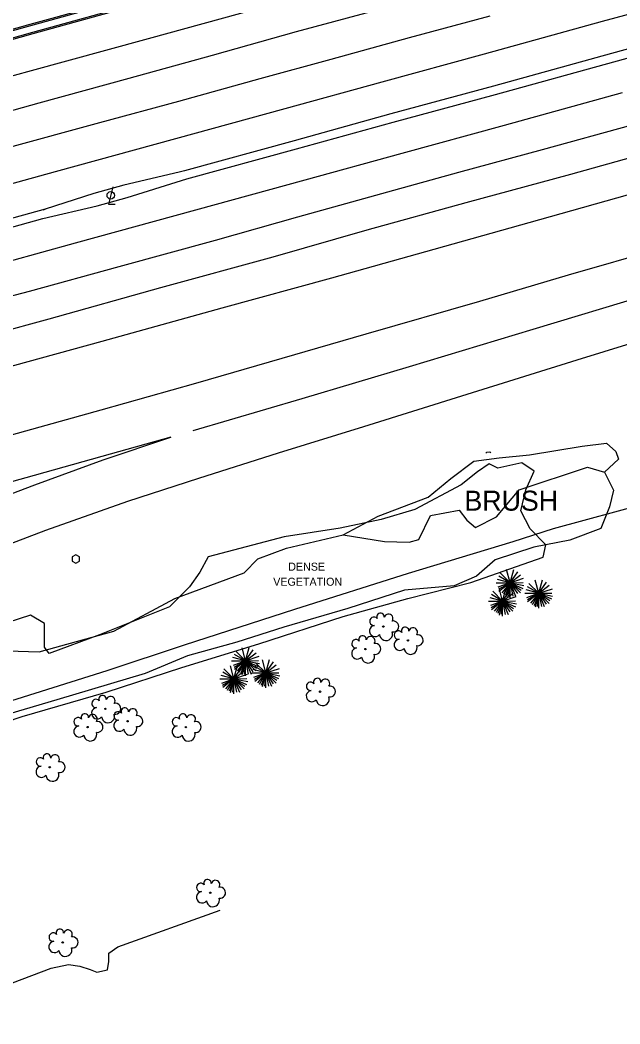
# Model space of a CAD drawing. Extents: x 2129547 to 2134906, y 657330 to 659734.
# Drawn here: x 2133105.8 to 2133315.8, y 658417.8 to 658769 of the extents above; entities that cross this region are included whole.
import ezdxf

# ---------------------------------------------------------------- set-up
doc = ezdxf.new("R2010")
doc.units = 0
for name, color, linetype in [('Default', 7, 'Continuous'), ('DR_X_Culvert', 7, 'Continuous'), ('LT_X_Poles', 7, 'Continuous'), ('PM_X_Edge_Line', 7, 'Continuous'), ('PM_X_Lane_Line', 7, 'Continuous'), ('PV_X_Curb', 7, 'Continuous'), ('PV_X_EOP2', 7, 'Continuous'), ('PV_X_Parking_Lot', 7, 'Continuous'), ('PV_X_Shoulder', 7, 'Continuous'), ('RD_X_Cells', 7, 'Continuous'), ('RD_X_Concrete_Barrier', 7, 'Continuous'), ('RD_X_Fence', 7, 'Continuous'), ('RD_X_Misc_Items', 7, 'Continuous'), ('VG_X_Cells', 7, 'Continuous'), ('VG_X_Shrub_Line_Lt', 7, 'Continuous'), ('VG_X_Text', 7, 'Continuous'), ('VG_X_Tree_Line_Lt', 7, 'Continuous')]:
    doc.layers.add(name, color=color, linetype=linetype)

# ---------------------------------------------------------------- blocks, each defined once
blk = doc.blocks.new('CULVERT')
at = {"layer": 'Default'}
blk.add_lwpolyline([(-0.0508, 0.1143), (0, 0.0635), (0, -0.0635), (-0.0508, -0.1143)], dxfattribs=at)
blk = doc.blocks.new('LPOLE')
at = {"layer": 'LT_X_Poles'}
blk.add_lwpolyline([(0.01, 0.0375), (-0.01, -0.0385), (0.02, -0.0385)], dxfattribs=at)
blk.add_circle((0, 0), 0.0165, dxfattribs=at)
blk = doc.blocks.new('POST')
at = {"layer": 'RD_X_Cells'}
blk.add_lwpolyline([(-0.0165, -0.0095), (0, -0.019), (0.0165, -0.0095), (0.0165, 0.0095), (0, 0.019), (-0.0165, 0.0095), (-0.0165, -0.0095)], dxfattribs=at)
blk = doc.blocks.new('TREE')
at = {"layer": 'VG_X_Cells'}
blk.add_circle((0, 0), 0.00305, dxfattribs=at)
for centre, radius, start, end in [((-0.0125, 0.0428), 0.0167, 354.0047, 205.9741), ((0.0232, 0.0359), 0.0197, 323.83, 165.0376), ((-0.0362, -0.0197), 0.0251, 96.1722, 320.5737), ((-0.042, 0.0237), 0.0187, 39.0625, 279.5412), ((0.0439, 0.0005), 0.0243, 259.1453, 101.4596), ((0.012, -0.0331), 0.029, 184.9476, 19.4572)]:
    blk.add_arc(centre, radius, start, end, dxfattribs=at)
blk = doc.blocks.new('ETREE')
at = {"layer": 'VG_X_Cells'}
for p, q in [((0, 0), (-0.0157, 0.0586)), ((0, 0), (0.016, 0.0597)), ((0, 0), (0.0337, 0.0493)), ((-0.0627, 0), (0, 0)), ((0, 0), (-0.056, 0.015)), ((0, 0), (-0.0545, -0.0198)), ((0, 0), (-0.0506, -0.029)), ((0, 0), (-0.0496, 0.0292)), ((0, 0), (-0.0496, -0.038)), ((0, 0), (-0.0443, 0.0443)), ((0, 0), (-0.0374, -0.044)), ((0, 0), (-0.0294, -0.051)), ((0, 0), (-0.0211, -0.0551)), ((0, 0), (-0.016, -0.0617)), ((0, 0), (-0.0069, -0.0583)), ((0, 0), (0.0464, 0.0356)), ((0, 0), (0.0602, 0.0204)), ((0, 0), (0.0573, 0.0012)), ((0, -0.0665), (0, 0)), ((0, 0), (0.0117, -0.0589)), ((0, 0), (0.0246, -0.0593)), ((0, 0), (0.0322, -0.0482)), ((0, 0), (0.0456, -0.0447)), ((0, 0), (0.0485, -0.0324)), ((0, 0), (0.0567, -0.0247)), ((0, 0), (0.0613, -0.0122))]:
    blk.add_line(p, q, dxfattribs=at)

msp = doc.modelspace()

# ---------------------------------------------------------------- linework, layer by layer
at = {"layer": 'PM_X_Edge_Line'}
for points in [[(2132528.76, 658591.3), (2132572.65, 658603.2), (2132602.55, 658611.29), (2132644.66, 658622.9), (2132678.49, 658632.23), (2132709.33, 658640.79), (2132742.09, 658649.84), (2132779.08, 658660.22), (2132814.09, 658669.97), (2132851.16, 658680.16), (2132885.72, 658689.68), (2132917.4, 658698.33), (2132953.49, 658708.38), (2132988.45, 658717.87), (2133023.88, 658727.48), (2133061.03, 658737.93), (2133108.53, 658751.04), (2133150.67, 658762.63), (2133188.97, 658773.11), (2133222.93, 658782.47), (2133258.8, 658792.21), (2133300.07, 658803.6), (2133337.89, 658813.96)], [(2132751.82, 658614.87), (2132788.85, 658625.26), (2132823.77, 658634.98), (2132860.8, 658645.16), (2132895.33, 658654.67), (2132927.05, 658663.34), (2132963.11, 658673.38), (2132997.96, 658682.83), (2133033.55, 658692.49), (2133070.77, 658702.96), (2133118.17, 658716.04), (2133160.28, 658727.62), (2133198.58, 658738.11), (2133232.5, 658747.46), (2133268.38, 658757.19), (2133309.7, 658768.6), (2133347.5, 658778.96)], [(2133316.59, 658743.53), (2133275.25, 658732.12), (2133239.36, 658722.38), (2133205.47, 658713.04), (2133167.16, 658702.55), (2133125.07, 658690.98), (2133077.75, 658677.91), (2133040.47, 658667.43), (2133004.77, 658657.74), (2132970.01, 658648.31), (2132933.96, 658638.28), (2132902.2, 658629.6), (2132867.7, 658620.1), (2132830.71, 658609.93), (2132795.85, 658600.22), (2132736.97, 658584.29), (2132686.86, 658570.47), (2132647.78, 658559.73), (2132616.38, 658551.02), (2132587.48, 658543.23), (2132543.98, 658531.22), (2132527.44, 658526.61)], [(2132526.73, 658488.71), (2132530.21, 658489.67), (2132569.63, 658500.53), (2132596.17, 658508.1), (2132621.44, 658515.22), (2132661.75, 658526.36), (2132698.15, 658536.48), (2132732.1, 658545.81), (2132769.52, 658556.2), (2132805.25, 658565.98), (2132840.18, 658575.71), (2132877.13, 658585.87), (2132911.6, 658595.36), (2132943.4, 658604.05), (2132979.41, 658614.08), (2133014.06, 658623.48), (2133049.93, 658633.21), (2133087.28, 658643.72), (2133134.5, 658656.75), (2133176.55, 658668.31), (2133214.88, 658678.81), (2133247.85, 658688.07), (2133283.96, 658698.16), (2133325.94, 658709.93)], [(2133330.15, 658689.11), (2133297.63, 658679.74), (2133266.56, 658670.62), (2133226.79, 658659.12), (2133197.42, 658650.62), (2133167.14, 658641.9), (2133134.04, 658632.57), (2133102.68, 658623.78), (2133072.24, 658615.25), (2133037.61, 658605.58), (2133003.5, 658596.32), (2132971.17, 658587.53), (2132944.96, 658580.31), (2132910.44, 658570.81), (2132883.46, 658563.38), (2132856.23, 658556.06), (2132824.38, 658546.99), (2132792.59, 658538.19), (2132761.91, 658529.84)], [(2132780.42, 658417.85), (2132794.53, 658428.85), (2132808.02, 658438.8), (2132828.29, 658452.89), (2132851.51, 658467.84), (2132872.43, 658480.36), (2132894.67, 658493.03), (2132919.61, 658506.34), (2132942.8, 658518.03), (2132970.58, 658531.41), (2132994.65, 658542.18), (2133023.55, 658554.71), (2133055.17, 658567.57), (2133087.49, 658580.23), (2133114.79, 658590.55), (2133143.49, 658600.71), (2133168.31, 658608.81), (2133196.23, 658617.63), (2133226.14, 658626.84), (2133262.28, 658638.19), (2133300.81, 658650.13), (2133340.17, 658662.31)], [(2133158.51, 658623.08), (2133137.32, 658617.18), (2133107.75, 658608.87), (2133069.12, 658598.17), (2133036.14, 658589.08), (2133001.62, 658579.74), (2132965.01, 658569.7), (2132930.32, 658560.06), (2132893.98, 658550.04), (2132857.01, 658539.9), (2132824.05, 658530.67), (2132784.28, 658519.67), (2132746.13, 658509.23), (2132706.06, 658498.15), (2132669.95, 658488.27), (2132635.09, 658478.56), (2132605.57, 658470.07), (2132586.69, 658464.73), (2132544.05, 658452.96), (2132525.87, 658448)], [(2132778.88, 658436.51), (2132797.28, 658450.31), (2132815.53, 658463.15), (2132834.09, 658475.32), (2132853.88, 658487.67), (2132874.62, 658499.37), (2132902.61, 658514.38), (2132925.64, 658526.53), (2132961.12, 658543.72), (2132996.4, 658559.86), (2133023.56, 658571.6), (2133058.45, 658586.09), (2133087.14, 658597.32), (2133091.83, 658599.15), (2133110.89, 658606.44), (2133134.83, 658615.24), (2133158.51, 658623.08)]]:
    msp.add_lwpolyline(points, dxfattribs=at)
at = {"layer": 'PM_X_Lane_Line'}
for points in [[(2132770.46, 658645.83), (2132797.06, 658653.26), (2132828.19, 658661.83), (2132861.38, 658670.87), (2132890.6, 658678.93), (2132920.35, 658687.14), (2132947.85, 658694.81), (2132974.67, 658702.08), (2133006.64, 658710.96), (2133034.51, 658718.68), (2133060.36, 658725.76), (2133088.12, 658733.33), (2133112.45, 658740.12), (2133143.94, 658748.72), (2133173.17, 658756.72), (2133202.56, 658765), (2133233.48, 658773.28)], [(2133270.18, 658770.37), (2133241.97, 658762.79), (2133214.5, 658755.19), (2133189.65, 658748.43), (2133161.27, 658740.52), (2133133.55, 658733.02), (2133100.64, 658724.1), (2133069.76, 658715.44), (2133037.24, 658706.34), (2133009.32, 658698.73), (2132981.91, 658691.14), (2132953.6, 658683.48), (2132924.09, 658675.45), (2132896.78, 658668.12), (2132864.32, 658659.21), (2132830.55, 658649.67), (2132796.16, 658640.09), (2132761.23, 658630.43)], [(2133319.94, 658732.31), (2133288.5, 658723.61), (2133259.3, 658715.66), (2133234.36, 658708.83), (2133202.83, 658700.05), (2133174.08, 658691.94), (2133140.33, 658682.75), (2133108.95, 658674.06), (2133082.6, 658667.15), (2133049.4, 658658.04), (2133018.8, 658649.85), (2132984.92, 658640.29), (2132949.38, 658630.35), (2132919.99, 658622.07), (2132890.94, 658613.99), (2132858.31, 658605.1), (2132836.54, 658599.14), (2132811.38, 658592.48), (2132777.26, 658582.97)], [(2133330.22, 658723.85), (2133298.5, 658714.96), (2133261.81, 658705.07), (2133227.15, 658695.47), (2133194.29, 658686.12), (2133154.93, 658675.36), (2133115.86, 658664.39), (2133078.14, 658654.11), (2133038.27, 658643.16), (2133002.28, 658632.99), (2132968.65, 658623.33), (2132933.53, 658613.55), (2132899.33, 658604.14), (2132864.71, 658594.55), (2132827.99, 658584.36), (2132790.39, 658574.06), (2132761.16, 658566.05), (2132724.86, 658555.97), (2132689.68, 658546.19), (2132656.96, 658537.15), (2132624.97, 658528.2), (2132593.37, 658519.4), (2132560.89, 658510.33), (2132526.97, 658501.13)], [(2133166.38, 658625.46), (2133204.56, 658636.6), (2133242.08, 658647.79), (2133285.43, 658660.84), (2133325.6, 658673.06)]]:
    msp.add_lwpolyline(points, dxfattribs=at)
at = {"layer": 'PV_X_Curb'}
for points in [[(2133354.62, 658834.11), (2133313.99, 658822.98), (2133249.15, 658805.18), (2133186.51, 658788.1), (2133148.3, 658777.86), (2133109.44, 658767.05), (2133075.85, 658757.65), (2133043.52, 658748.97), (2133012.69, 658740.69), (2132981.33, 658732.09), (2132950.79, 658723.65), (2132920.09, 658715.1), (2132889.35, 658706.83), (2132858.99, 658698.27), (2132820.58, 658687.77), (2132782.52, 658677.48), (2132742.93, 658666.63), (2132707.48, 658656.83), (2132668.28, 658645.96), (2132633.36, 658636.51), (2132602.69, 658628.08)], [(2133355.25, 658831.69), (2133314.65, 658820.57), (2133249.81, 658802.77), (2133187.16, 658785.68), (2133148.96, 658775.45), (2133110.11, 658764.65), (2133076.51, 658755.24), (2133044.17, 658746.56), (2133013.34, 658738.28), (2132981.99, 658729.68), (2132951.45, 658721.24), (2132920.75, 658712.69), (2132890.01, 658704.42), (2132859.66, 658695.87), (2132821.24, 658685.36), (2132783.18, 658675.06), (2132743.6, 658664.22), (2132708.14, 658654.42), (2132668.94, 658643.55), (2132634.02, 658634.09), (2132603.1, 658625.87)]]:
    msp.add_lwpolyline(points, dxfattribs=at)
at = {"layer": 'PV_X_EOP2'}
for points in [[(2132528.76, 658591.3), (2132572.65, 658603.2), (2132602.55, 658611.29), (2132644.66, 658622.9), (2132678.49, 658632.23), (2132709.33, 658640.79), (2132742.09, 658649.84), (2132779.08, 658660.22), (2132814.09, 658669.97), (2132851.16, 658680.16), (2132885.72, 658689.68), (2132917.4, 658698.33), (2132953.49, 658708.38), (2132988.45, 658717.87), (2133023.88, 658727.48), (2133061.03, 658737.93), (2133108.53, 658751.04), (2133150.67, 658762.63), (2133188.97, 658773.11), (2133222.93, 658782.47), (2133258.8, 658792.21), (2133300.07, 658803.6), (2133337.89, 658813.96)], [(2132751.82, 658614.87), (2132788.85, 658625.26), (2132823.77, 658634.98), (2132860.8, 658645.16), (2132895.33, 658654.67), (2132927.05, 658663.34), (2132963.11, 658673.38), (2132997.96, 658682.83), (2133033.55, 658692.49), (2133070.77, 658702.96), (2133118.17, 658716.04), (2133160.28, 658727.62), (2133198.58, 658738.11), (2133232.5, 658747.46), (2133268.38, 658757.19), (2133309.7, 658768.6), (2133347.5, 658778.96)], [(2133316.59, 658743.53), (2133275.25, 658732.12), (2133239.36, 658722.38), (2133205.47, 658713.04), (2133167.16, 658702.55), (2133125.07, 658690.98), (2133077.75, 658677.91), (2133040.47, 658667.43), (2133004.77, 658657.74), (2132970.01, 658648.31), (2132933.96, 658638.28), (2132902.2, 658629.6), (2132867.7, 658620.1), (2132830.71, 658609.93), (2132795.85, 658600.22), (2132736.97, 658584.29), (2132686.86, 658570.47), (2132647.78, 658559.73), (2132616.38, 658551.02), (2132587.48, 658543.23), (2132543.98, 658531.22), (2132527.44, 658526.61)], [(2132526.73, 658488.71), (2132530.21, 658489.67), (2132569.63, 658500.53), (2132596.17, 658508.1), (2132621.44, 658515.22), (2132661.75, 658526.36), (2132698.15, 658536.48), (2132732.1, 658545.81), (2132769.52, 658556.2), (2132805.25, 658565.98), (2132840.18, 658575.71), (2132877.13, 658585.87), (2132911.6, 658595.36), (2132943.4, 658604.05), (2132979.41, 658614.08), (2133014.06, 658623.48), (2133049.93, 658633.21), (2133087.28, 658643.72), (2133134.5, 658656.75), (2133176.55, 658668.31), (2133214.88, 658678.81), (2133247.85, 658688.07), (2133283.96, 658698.16), (2133325.94, 658709.93)], [(2133330.15, 658689.11), (2133297.63, 658679.74), (2133266.56, 658670.62), (2133226.79, 658659.12), (2133197.42, 658650.62), (2133167.14, 658641.9), (2133134.04, 658632.57), (2133102.68, 658623.78), (2133072.24, 658615.25), (2133037.61, 658605.58), (2133003.5, 658596.32), (2132971.17, 658587.53), (2132944.96, 658580.31), (2132910.44, 658570.81), (2132883.46, 658563.38), (2132856.23, 658556.06), (2132824.38, 658546.99), (2132792.59, 658538.19), (2132761.91, 658529.84)]]:
    msp.add_lwpolyline(points, dxfattribs=at)
at = {"layer": 'PV_X_Parking_Lot'}
msp.add_lwpolyline([(2133103.14, 658432.24), (2133116.7, 658437.31), (2133122.67, 658438.61), (2133126.66, 658438.11), (2133130.28, 658436.89), (2133132.68, 658435.98), (2133136.39, 658436.82), (2133136.81, 658439.63), (2133136.81, 658442.59), (2133140.02, 658444.8), (2133175.8, 658457.64)], dxfattribs=at)
at = {"layer": 'PV_X_Shoulder'}
for points in [[(2132602.56, 658628.56), (2132633.23, 658636.99), (2132668.15, 658646.45), (2132707.34, 658657.31), (2132742.8, 658667.11), (2132782.39, 658677.96), (2132820.45, 658688.26), (2132858.86, 658698.76), (2132889.22, 658707.31), (2132919.96, 658715.58), (2132950.65, 658724.13), (2132981.19, 658732.57), (2133012.56, 658741.17), (2133043.39, 658749.45), (2133075.72, 658758.13), (2133109.31, 658767.54), (2133148.17, 658778.35), (2133186.38, 658788.58), (2133249.02, 658805.67), (2133313.86, 658823.46), (2133354.5, 658834.6)], [(2133355.38, 658831.21), (2133314.78, 658820.09), (2133249.94, 658802.29), (2133187.29, 658785.2), (2133149.09, 658774.97), (2133110.25, 658764.16), (2133076.65, 658754.76), (2133044.3, 658746.07), (2133013.47, 658737.79), (2132982.12, 658729.2), (2132951.59, 658720.76), (2132920.88, 658712.21), (2132890.15, 658703.93), (2132859.8, 658695.38), (2132821.37, 658684.88), (2132783.31, 658674.58), (2132743.73, 658663.74), (2132708.28, 658653.94), (2132669.07, 658643.07), (2132634.15, 658633.61), (2132603.23, 658625.39)]]:
    msp.add_lwpolyline(points, dxfattribs=at)
at = {"layer": 'RD_X_Concrete_Barrier'}
msp.add_line((2133113.8, 658702.67), (2133114.6, 658702.92), dxfattribs=at)
for points in [[(2133350.6, 658767.68), (2133312.8, 658757.32), (2133271.47, 658745.91), (2133235.59, 658736.17), (2133201.68, 658726.83), (2133163.38, 658716.34), (2133161.51, 658715.82), (2133142.13, 658711.26), (2133131.55, 658708.34), (2133114.6, 658702.92)], [(2132733.99, 658595.19), (2132792.86, 658611.11), (2132827.69, 658620.82), (2132864.7, 658630.99), (2132899.22, 658640.5), (2132930.96, 658649.17), (2132967.01, 658659.2), (2133001.81, 658668.65), (2133037.46, 658678.32), (2133074.72, 658688.8), (2133113.76, 658699.58), (2133132.75, 658704), (2133143.27, 658706.9), (2133162.3, 658712.93), (2133164.17, 658713.44), (2133202.48, 658723.94), (2133236.38, 658733.28), (2133272.26, 658743.02), (2133313.6, 658754.43), (2133351.4, 658764.78)], [(2133114.6, 658702.92), (2133073.91, 658691.69), (2133036.67, 658681.21), (2133001.02, 658671.54), (2132966.22, 658662.09), (2132930.16, 658652.06), (2132898.42, 658643.39), (2132863.91, 658633.88), (2132826.89, 658623.71), (2132792.07, 658614.01), (2132733.2, 658598.09), (2132728.03, 658596.66), (2132708.65, 658592.09), (2132698.07, 658589.17), (2132680.32, 658583.5), (2132643.98, 658573.52), (2132612.61, 658564.81), (2132584.03, 658557.2), (2132559.64, 658550.51), (2132527.73, 658542.1)]]:
    msp.add_lwpolyline(points, dxfattribs=at)
at = {"layer": 'RD_X_Fence'}
msp.add_lwpolyline([(2133409.37, 658623.24), (2133399.25, 658620.39), (2133396.55, 658620.65), (2133384.38, 658617.74), (2133380.03, 658615.44), (2133356.03, 658608.88), (2133325.9, 658600.19), (2133292.34, 658590.99), (2133278.32, 658586.5), (2133241.59, 658575.44), (2133201.86, 658562.85), (2133163.22, 658550.3), (2133136.09, 658541.38), (2133085.63, 658525.47), (2133059.75, 658517.07), (2133037.1, 658508.29), (2133014.93, 658496.51), (2132978.92, 658478.61), (2132972.42, 658487.07)], dxfattribs=at)
at = {"layer": 'RD_X_Misc_Items'}
msp.add_lwpolyline([(2133088.23, 658519.27), (2133106.48, 658525.38), (2133135.85, 658533.94), (2133162.34, 658542.48), (2133189.4, 658550.78), (2133218.83, 658560.43), (2133241.47, 658566.72), (2133263.53, 658572.24), (2133288.9, 658581.12), (2133289.88, 658585.42), (2133284.3, 658590.99), (2133281.12, 658597.31), (2133282.78, 658604.66), (2133285.69, 658611.21), (2133281.45, 658614.18), (2133273.03, 658612.32), (2133269.98, 658613.79), (2133265.93, 658611.04), (2133260.2, 658606.49), (2133244.01, 658597.84), (2133232.21, 658594.26), (2133217.79, 658591.24), (2133198.2, 658588.23), (2133171.59, 658581.23), (2133168.69, 658575.87), (2133165.02, 658570.73), (2133158.04, 658563.75), (2133133.53, 658553.97), (2133115.95, 658547.4), (2133114.29, 658549.63), (2133114.3, 658551.41), (2133114.31, 658557.87), (2133109.38, 658560.89), (2133089.43, 658554.39)], dxfattribs=at)
at = {"layer": 'VG_X_Shrub_Line_Lt'}
msp.add_lwpolyline([(2133218.88, 658588.99), (2133231.12, 658595.43), (2133248.61, 658602.14), (2133256.51, 658608.62), (2133264.67, 658614.77), (2133273.45, 658615.93), (2133284.13, 658616.95), (2133302.58, 658619.95), (2133311.05, 658620.97), (2133314.34, 658618.14), (2133315.22, 658615.41), (2133310.32, 658610.87)], dxfattribs=at)
at = {"layer": 'VG_X_Tree_Line_Lt'}
msp.add_lwpolyline([(2133101.39, 658548.42), (2133112.42, 658547.98), (2133138.64, 658555.21), (2133159.99, 658566.66), (2133184.17, 658575.62), (2133188.96, 658580.53), (2133199.04, 658584.33), (2133218.88, 658588.99), (2133233.37, 658586.57), (2133241.98, 658586.33), (2133245.37, 658587.37), (2133249.4, 658595.69), (2133259.45, 658597.62), (2133262.15, 658594.09), (2133265.16, 658591.49), (2133272.54, 658595.25), (2133280.52, 658604.64), (2133304.42, 658612.61), (2133310.32, 658610.87), (2133313.53, 658604.6), (2133312.09, 658598.75), (2133309.08, 658591.16), (2133298.19, 658587.07), (2133285.6, 658584.65), (2133272.07, 658580.16), (2133265.56, 658574.43), (2133257.68, 658571.15), (2133240.37, 658569.56), (2133220.49, 658563.2), (2133198.06, 658556.68), (2133181.7, 658551.41), (2133164.42, 658546.58), (2133149.53, 658540.49), (2133118.64, 658531.19), (2133095.67, 658524.41)], dxfattribs=at)

# ---------------------------------------------------------------- block references
at = {"layer": 'DR_X_Culvert', "xscale": 7.873999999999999, "yscale": 7.874000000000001, "rotation": 92.39702855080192}
msp.add_blockref('CULVERT', (2133269.7, 658617.94), dxfattribs=at)
at = {"layer": 'LT_X_Poles', "xscale": 78.74000000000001, "yscale": 78.74000000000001}
msp.add_blockref('LPOLE', (2133137.5, 658707.71), dxfattribs=at)
at = {"layer": 'RD_X_Cells', "xscale": 78.74000000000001, "yscale": 78.74000000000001}
msp.add_blockref('POST', (2133125.32, 658580.49), dxfattribs=at)
at = {"layer": 'VG_X_Cells', "xscale": 78.74000000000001, "yscale": 78.74000000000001}
for name, p in [('ETREE', (2133277.32, 658572.17)), ('ETREE', (2133287.36, 658568.49)), ('ETREE', (2133274.71, 658565.75)), ('TREE', (2133232.94, 658556.86)), ('TREE', (2133241.53, 658552.02)), ('TREE', (2133226.66, 658548.99)), ('ETREE', (2133184.71, 658544.84)), ('ETREE', (2133191.82, 658540.62)), ('ETREE', (2133180.62, 658538.55)), ('TREE', (2133210.78, 658534.08)), ('TREE', (2133135.63, 658528.08)), ('TREE', (2133143.39, 658523.75)), ('TREE', (2133129.4, 658521.7)), ('TREE', (2133163.79, 658521.67)), ('TREE', (2133116.16, 658507.62)), ('TREE', (2133172.33, 658463.72)), ('TREE', (2133120.68, 658446.35))]:
    msp.add_blockref(name, p, dxfattribs=at)

# ---------------------------------------------------------------- texts
at = {"layer": 'VG_X_Text'}
for s, height, p in [('BRUSH', 7, (2133261.34, 658597.39)), ('DENSE', 2.8, (2133199.64, 658576.41)), ('VEGETATION', 2.8, (2133194.39, 658571.14))]:
    msp.add_text(s, height=height, dxfattribs=at).set_placement(p)

doc.saveas('drawing.dxf')
